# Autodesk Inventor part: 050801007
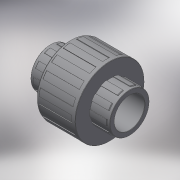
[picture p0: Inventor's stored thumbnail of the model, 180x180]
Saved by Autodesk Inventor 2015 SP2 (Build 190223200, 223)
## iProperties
Created: 2017-10
Part Number: 050801007
Material: Generic
Description: PLASSON THR.UNION+O RING PVC 3/4''
Document SubType Name: Modeling
Designer: KIM
Density: 1 g/cm^3
Appearance: Default
Author: KIM
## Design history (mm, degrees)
derived "050801.ipt"
feature "Solid1::050801.ipt"
tag "TaggingFeature1"
body "Solid1"
other parameters: "d0" = 51, "d3" = 24.117, "d4" = 24.117, "d5" = 32.31678, "d6" = 31.34728, "d7" = 32.31678, "d8" = 52, "d10" = 18, "d11" = 21.7053, "d14" = 13.5, "d17" = 1.8, "d19" = 50.96, "d20" = 1.8, "d21" = 0.78, "d25" = 5.2, "d26" = 2.6, "d27" = 19.98, "d28" = 0, "d32" = 5.2, "d33" = 2.6, "d35" = 0, "d39" = 0.16, "d45" = 0.48475, "d49" = 360 deg, "d51" = 0.52, "d55" = 360 deg, "d57" = 18, "d58" = 13.5, "d_" = 16, "E_" = 52, "H_" = 51, "l_" = 14, "lt_" = 18, "Z_" = 11, "G_" = 24.117, "d24" = 22.2, "d40" = 0.48475, "d44" = 0.52
